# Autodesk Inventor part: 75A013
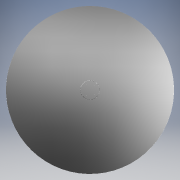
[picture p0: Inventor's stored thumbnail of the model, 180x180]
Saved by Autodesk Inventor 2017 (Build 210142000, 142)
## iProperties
Created: 2021-10
Part Number: 75A013
Material: Generico
Document SubType Name: Modeling
Designer: PIZZERA
Density: 1 g/cm^3
Appearance: Default
Author: PIZZERA
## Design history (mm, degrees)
feature "Base1"
node "Solido1"
node "Solido2"
